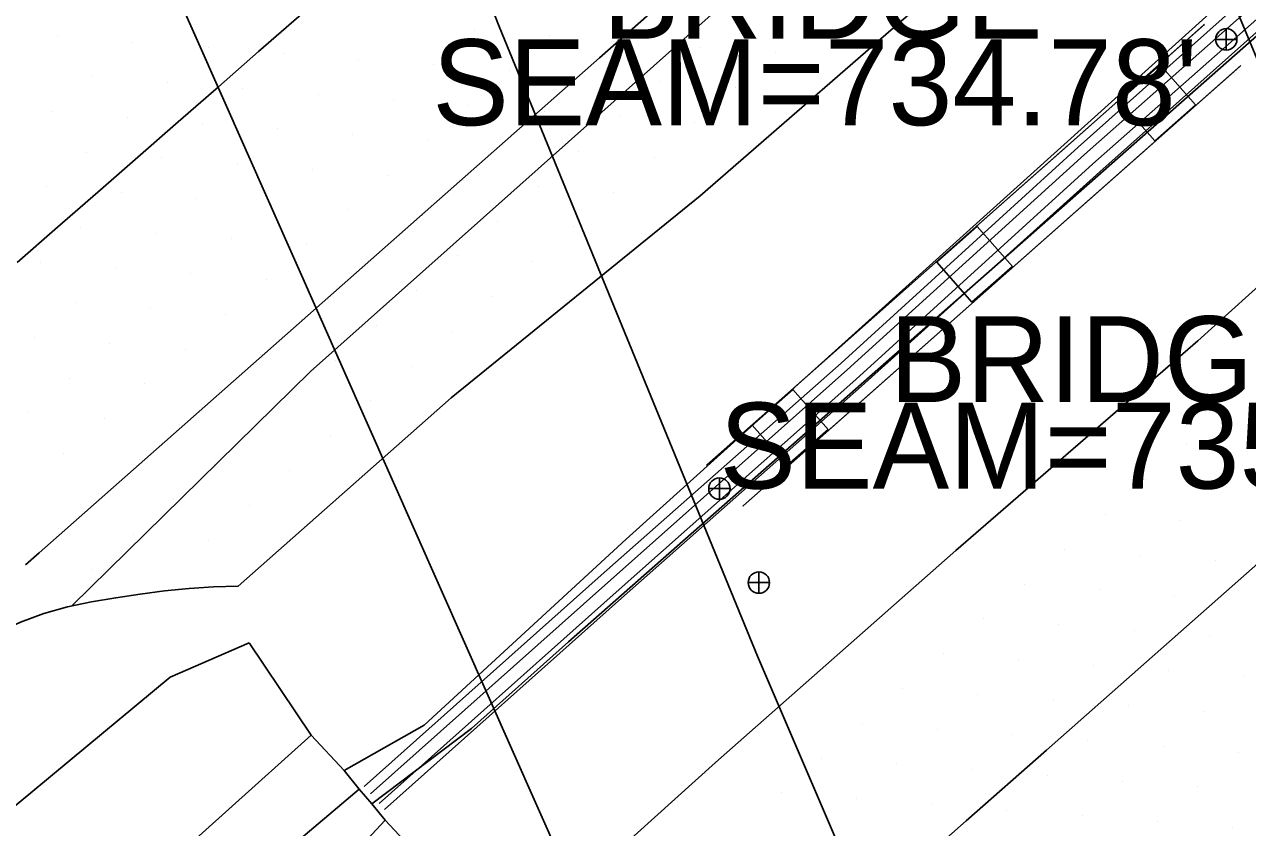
# Model space of a CAD drawing. Extents: x 1548934 to 1561348, y 809680 to 824075.
# Drawn here: x 1551783.3 to 1551840.5, y 810705.8 to 810743.4 of the extents above; entities that cross this region are included whole.
import ezdxf

# ---------------------------------------------------------------- set-up
doc = ezdxf.new("R2010")
doc.units = 0
for name, color, linetype in [('Default', 7, 'Continuous'), ('E_NCDOT_Vertical_Profile_Ground_Line', 7, 'Continuous'), ('Exist DTM Scan Elevation Point', 7, 'Continuous'), ('Exist Other Culture Area Outline', 7, 'Continuous'), ('Exist Structure Major Bridge Seam Top Elevation', 7, 'Continuous'), ('Exist Structure Major Deck Tunnel Box Culvert', 7, 'Continuous'), ('P_RDY_Terminator_Cell', 7, 'Continuous'), ('Pattern_8', 7, 'Continuous'), ('PH Exist DTM Breakline', 7, 'Continuous')]:
    doc.layers.add(name, color=color, linetype=linetype)

# ---------------------------------------------------------------- blocks, each defined once
blk = doc.blocks.new('SurveyPointCell')
at = {"layer": 'Default'}
for p, q in [((-0.5, 0), (0.5, 0)), ((0, -0.5), (0, 0.5))]:
    blk.add_line(p, q, dxfattribs=at)
blk.add_circle((0, 0), 0.5, dxfattribs=at)

msp = doc.modelspace()

# ---------------------------------------------------------------- linework, layer by layer
at = {"layer": 'E_NCDOT_Vertical_Profile_Ground_Line'}
for points in [[(1551730.822, 810673.853), (1551753.618, 810693.379), (1551776.873, 810712.355), (1551777.906, 810712.877), (1551778.938, 810713.401), (1551779.968, 810713.927), (1551780.996, 810714.457), (1551782.03, 810714.977), (1551783.082, 810715.455), (1551784.165, 810715.86), (1551785.276, 810716.172), (1551786.405, 810716.412), (1551787.541, 810716.606), (1551788.679, 810716.776), (1551789.821, 810716.924), (1551790.968, 810717.039), (1551792.121, 810717.111), (1551793.277, 810717.148), (1551803.243, 810725.955), (1551814.903, 810735.412), (1551826.218, 810745.259), (1551837.521, 810755.119), (1551848.5, 810765.046)], [(1551808.004, 810702.031), (1551815.623, 810708.894), (1551826.873, 810718.815), (1551838.214, 810728.632), (1551849.35, 810738.682)]]:
    msp.add_lwpolyline(points, dxfattribs=at)
at = {"layer": 'Exist DTM Scan Elevation Point'}
for p, q in [((1551804.334, 810743.172), (1551804.334, 810743.172)), ((1551784.81, 810742.88), (1551784.81, 810742.88)), ((1551788.335, 810742.612), (1551788.335, 810742.612)), ((1551807.86, 810742.905), (1551807.86, 810742.905)), ((1551811.387, 810742.639), (1551811.387, 810742.639)), ((1551791.86, 810742.345), (1551791.86, 810742.345)), ((1551795.386, 810742.077), (1551795.386, 810742.077)), ((1551814.914, 810742.373), (1551814.914, 810742.373)), ((1551818.442, 810742.107), (1551818.442, 810742.107)), ((1551798.912, 810741.81), (1551798.912, 810741.81)), ((1551802.438, 810741.543), (1551802.438, 810741.543)), ((1551805.964, 810741.276), (1551805.964, 810741.276)), ((1551786.439, 810740.983), (1551786.439, 810740.983)), ((1551789.964, 810740.716), (1551789.964, 810740.716)), ((1551809.49, 810741.01), (1551809.49, 810741.01)), ((1551813.018, 810740.744), (1551813.018, 810740.744)), ((1551793.49, 810740.449), (1551793.49, 810740.449)), ((1551797.015, 810740.181), (1551797.015, 810740.181)), ((1551816.545, 810740.479), (1551816.545, 810740.479)), ((1551800.541, 810739.914), (1551800.541, 810739.914)), ((1551804.067, 810739.647), (1551804.067, 810739.647)), ((1551784.542, 810739.354), (1551784.542, 810739.354)), ((1551788.068, 810739.087), (1551788.068, 810739.087)), ((1551807.594, 810739.381), (1551807.594, 810739.381)), ((1551811.121, 810739.115), (1551811.121, 810739.115)), ((1551791.593, 810738.82), (1551791.593, 810738.82)), ((1551795.119, 810738.553), (1551795.119, 810738.553)), ((1551814.649, 810738.85), (1551814.649, 810738.85)), ((1551798.645, 810738.286), (1551798.645, 810738.286)), ((1551802.171, 810738.019), (1551802.171, 810738.019)), ((1551786.171, 810737.458), (1551786.171, 810737.458)), ((1551805.698, 810737.752), (1551805.698, 810737.752)), ((1551809.225, 810737.486), (1551809.225, 810737.486)), ((1551789.697, 810737.191), (1551789.697, 810737.191)), ((1551793.223, 810736.924), (1551793.223, 810736.924)), ((1551812.753, 810737.221), (1551812.753, 810737.221)), ((1551796.749, 810736.657), (1551796.749, 810736.657)), ((1551800.275, 810736.39), (1551800.275, 810736.39)), ((1551803.801, 810736.123), (1551803.801, 810736.123)), ((1551784.275, 810735.829), (1551784.275, 810735.829)), ((1551787.8, 810735.562), (1551787.8, 810735.562)), ((1551807.328, 810735.857), (1551807.328, 810735.857)), ((1551810.855, 810735.591), (1551810.855, 810735.591)), ((1551791.326, 810735.295), (1551791.326, 810735.295)), ((1551794.852, 810735.028), (1551794.852, 810735.028)), ((1551798.378, 810734.761), (1551798.378, 810734.761)), ((1551801.905, 810734.494), (1551801.905, 810734.494)), ((1551785.904, 810733.933), (1551785.904, 810733.933)), ((1551805.432, 810734.228), (1551805.432, 810734.228)), ((1551808.959, 810733.963), (1551808.959, 810733.963)), ((1551789.43, 810733.666), (1551789.43, 810733.666)), ((1551792.956, 810733.399), (1551792.956, 810733.399)), ((1551796.482, 810733.132), (1551796.482, 810733.132)), ((1551800.008, 810732.865), (1551800.008, 810732.865)), ((1551784.008, 810732.304), (1551784.008, 810732.304)), ((1551803.536, 810732.6), (1551803.536, 810732.6)), ((1551807.063, 810732.333), (1551807.063, 810732.333)), ((1551787.534, 810732.037), (1551787.534, 810732.037)), ((1551791.06, 810731.77), (1551791.06, 810731.77)), ((1551794.585, 810731.503), (1551794.585, 810731.503)), ((1551798.112, 810731.236), (1551798.112, 810731.236)), ((1551801.639, 810730.97), (1551801.639, 810730.97)), ((1551785.637, 810730.408), (1551785.637, 810730.408)), ((1551805.168, 810730.706), (1551805.168, 810730.706)), ((1551789.163, 810730.141), (1551789.163, 810730.141)), ((1551792.689, 810729.874), (1551792.689, 810729.874)), ((1551796.215, 810729.607), (1551796.215, 810729.607)), ((1551799.743, 810729.341), (1551799.743, 810729.341)), ((1551783.741, 810728.779), (1551783.741, 810728.779)), ((1551803.27, 810729.076), (1551803.27, 810729.076)), ((1551839.82, 810728.913), (1551839.82, 810728.913)), ((1551787.267, 810728.512), (1551787.267, 810728.512)), ((1551790.793, 810728.245), (1551790.793, 810728.245)), ((1551794.319, 810727.979), (1551794.319, 810727.979)), ((1551797.846, 810727.712), (1551797.846, 810727.712)), ((1551801.374, 810727.447), (1551801.374, 810727.447)), ((1551785.37, 810726.883), (1551785.37, 810726.883)), ((1551788.896, 810726.616), (1551788.896, 810726.616)), ((1551792.423, 810726.35), (1551792.423, 810726.35)), ((1551795.95, 810726.084), (1551795.95, 810726.084)), ((1551799.477, 810725.817), (1551799.477, 810725.817)), ((1551783.474, 810725.254), (1551783.474, 810725.254)), ((1551839.551, 810725.386), (1551839.551, 810725.386)), ((1551787, 810724.987), (1551787, 810724.987)), ((1551790.527, 810724.721), (1551790.527, 810724.721)), ((1551794.054, 810724.455), (1551794.054, 810724.455)), ((1551797.582, 810724.189), (1551797.582, 810724.189)), ((1551837.655, 810723.757), (1551837.655, 810723.757)), ((1551785.103, 810723.358), (1551785.103, 810723.358)), ((1551788.63, 810723.092), (1551788.63, 810723.092)), ((1551792.158, 810722.826), (1551792.158, 810722.826)), ((1551795.685, 810722.56), (1551795.685, 810722.56)), ((1551835.759, 810722.128), (1551835.759, 810722.128)), ((1551839.282, 810721.859), (1551839.282, 810721.859)), ((1551786.734, 810721.463), (1551786.734, 810721.463)), ((1551790.261, 810721.197), (1551790.261, 810721.197)), ((1551793.789, 810720.931), (1551793.789, 810720.931)), ((1551833.862, 810720.499), (1551833.862, 810720.499)), ((1551837.386, 810720.23), (1551837.386, 810720.23)), ((1551784.837, 810719.834), (1551784.837, 810719.834)), ((1551788.364, 810719.568), (1551788.364, 810719.568)), ((1551791.892, 810719.302), (1551791.892, 810719.302)), ((1551831.966, 810718.87), (1551831.966, 810718.87)), ((1551835.49, 810718.601), (1551835.49, 810718.601)), ((1551786.468, 810717.939), (1551786.468, 810717.939)), ((1551839.013, 810718.332), (1551839.013, 810718.332)), ((1551830.07, 810717.241), (1551830.07, 810717.241)), ((1551833.593, 810716.973), (1551833.593, 810716.973)), ((1551837.117, 810716.704), (1551837.117, 810716.704)), ((1551828.173, 810715.613), (1551828.173, 810715.613)), ((1551831.697, 810715.344), (1551831.697, 810715.344)), ((1551835.221, 810715.075), (1551835.221, 810715.075)), ((1551838.745, 810714.806), (1551838.745, 810714.806)), ((1551826.277, 810713.984), (1551826.277, 810713.984)), ((1551829.801, 810713.715), (1551829.801, 810713.715)), ((1551833.324, 810713.446), (1551833.324, 810713.446)), ((1551836.848, 810713.177), (1551836.848, 810713.177)), ((1551840.373, 810712.909), (1551840.373, 810712.909)), ((1551824.381, 810712.355), (1551824.381, 810712.355)), ((1551827.904, 810712.086), (1551827.904, 810712.086)), ((1551831.428, 810711.817), (1551831.428, 810711.817)), ((1551834.952, 810711.548), (1551834.952, 810711.548)), ((1551838.477, 810711.28), (1551838.477, 810711.28)), ((1551822.484, 810710.726), (1551822.484, 810710.726)), ((1551826.008, 810710.457), (1551826.008, 810710.457)), ((1551829.532, 810710.188), (1551829.532, 810710.188)), ((1551833.056, 810709.919), (1551833.056, 810709.919)), ((1551836.58, 810709.651), (1551836.58, 810709.651)), ((1551840.105, 810709.383), (1551840.105, 810709.383)), ((1551820.588, 810709.097), (1551820.588, 810709.097)), ((1551824.112, 810708.828), (1551824.112, 810708.828)), ((1551827.635, 810708.559), (1551827.635, 810708.559)), ((1551831.159, 810708.29), (1551831.159, 810708.29)), ((1551818.691, 810707.468), (1551818.691, 810707.468)), ((1551834.684, 810708.022), (1551834.684, 810708.022)), ((1551838.208, 810707.754), (1551838.208, 810707.754)), ((1551822.215, 810707.199), (1551822.215, 810707.199)), ((1551825.739, 810706.93), (1551825.739, 810706.93)), ((1551829.263, 810706.661), (1551829.263, 810706.661)), ((1551832.787, 810706.393), (1551832.787, 810706.393)), ((1551836.312, 810706.125), (1551836.312, 810706.125)), ((1551839.837, 810705.857), (1551839.837, 810705.857))]:
    msp.add_line(p, q, dxfattribs=at)
at = {"layer": 'Exist Other Culture Area Outline'}
msp.add_lwpolyline([(1551793.783, 810714.49), (1551796.686, 810710.178), (1551798.234, 810708.524), (1551798.935, 810707.649), (1551799.527, 810706.96), (1551800.147, 810706.191), (1551801.479, 810704.775), (1551803.631, 810702.658), (1551805.5, 810701.282)], dxfattribs=at)
at = {"layer": 'Exist Structure Major Deck Tunnel Box Culvert'}
for points in [[(1551890.16, 810628.772), (1551869.489, 810674.52), (1551854.065, 810710.393), (1551839.842, 810744.541), (1551817.227, 810801.667), (1551801.118, 810844.761), (1551789.242, 810877.577)], [(1551763.353, 810854.68), (1551776.069, 810819.842), (1551783.152, 810800.687), (1551795.344, 810769.157), (1551805.495, 810743.337), (1551817.592, 810713.867), (1551830.145, 810684.596), (1551846.388, 810647.478), (1551862.114, 810612.886), (1551864.95, 810606.898)]]:
    msp.add_lwpolyline(points, dxfattribs=at)
for points in [[(1551838.515, 810743.432), (1551815.213, 810722.818), (1551815.213, 810722.818), (1551818.269, 810725.521), (1551818.269, 810725.521), (1551825.095, 810731.56), (1551825.095, 810731.56), (1551831.838, 810737.525), (1551831.838, 810737.525), (1551838.475, 810743.396)], [(1551840.22, 810741.511), (1551816.917, 810720.898), (1551816.917, 810720.898), (1551819.973, 810723.601), (1551819.973, 810723.601), (1551826.8, 810729.64), (1551826.8, 810729.64), (1551833.543, 810735.604), (1551833.543, 810735.604), (1551840.179, 810741.475)], [(1551838.094, 810739.67), (1551836.193, 810737.992), (1551834.543, 810739.861), (1551836.444, 810741.539)], [(1551829.529, 810732.115), (1551827.629, 810730.438), (1551825.979, 810732.307), (1551827.88, 810733.984)], [(1551820.895, 810724.485), (1551818.995, 810722.807), (1551817.345, 810724.676), (1551819.246, 810726.354)]]:
    msp.add_lwpolyline(points, close=True, dxfattribs=at)
at = {"layer": 'P_RDY_Terminator_Cell'}
for points in [[(1551854.512, 810780.962), (1551852.912, 810779.601), (1551849.914, 810776.954), (1551846.916, 810774.306), (1551840.17, 810768.349), (1551836.422, 810765.04), (1551832.674, 810761.73), (1551828.926, 810758.421), (1551825.178, 810755.111), (1551821.431, 810751.802), (1551817.683, 810748.492), (1551813.935, 810745.183), (1551810.187, 810741.873), (1551806.439, 810738.564), (1551802.692, 810735.254), (1551795.196, 810728.635), (1551791.448, 810725.326), (1551787.7, 810722.017), (1551783.953, 810718.707), (1551783.318, 810718.146)], [(1551820.539, 810765.242), (1551818.66, 810763.594), (1551816.78, 810761.945), (1551814.901, 810760.297), (1551813.021, 810758.648), (1551811.142, 810757), (1551809.262, 810755.352), (1551807.382, 810753.703), (1551805.503, 810752.055), (1551803.623, 810750.406), (1551801.744, 810748.758), (1551799.864, 810747.11), (1551797.985, 810745.461), (1551796.105, 810743.813), (1551794.226, 810742.164), (1551792.346, 810740.516), (1551790.463, 810738.872), (1551788.578, 810737.229), (1551786.694, 810735.586), (1551784.81, 810733.943), (1551782.925, 810732.3)], [(1551854.975, 810757.675), (1551843.796, 810747.674), (1551832.599, 810737.693), (1551821.511, 810727.588), (1551810.27, 810717.657), (1551799.168, 810707.769)], [(1551855.42, 810757.218), (1551844.155, 810747.31), (1551832.897, 810737.352), (1551821.785, 810727.271), (1551810.575, 810717.321), (1551799.474, 810707.426)], [(1551855.807, 810756.759), (1551844.541, 810746.851), (1551833.297, 810736.905), (1551822.186, 810726.825), (1551810.973, 810716.872), (1551799.873, 810706.978)], [(1551856.295, 810756.179), (1551844.812, 810746.522), (1551833.621, 810736.534), (1551822.461, 810726.511), (1551811.222, 810716.578), (1551800.129, 810706.691)], [(1551878.836, 810751.55), (1551876.115, 810749.151), (1551868.615, 810742.538), (1551864.865, 810739.231), (1551861.115, 810735.924), (1551857.365, 810732.617), (1551853.615, 810729.31), (1551849.865, 810726.003), (1551842.365, 810719.389), (1551838.615, 810716.082), (1551834.865, 810712.775), (1551831.115, 810709.468), (1551827.366, 810706.161), (1551823.616, 810702.854), (1551816.116, 810696.24), (1551812.366, 810692.933), (1551810.993, 810691.723)]]:
    msp.add_lwpolyline(points, dxfattribs=at)
at = {"layer": 'Pattern_8'}
msp.add_lwpolyline([(1551772.004, 810786.253), (1551837.927, 810637.788)], dxfattribs=at)
at = {"layer": 'PH Exist DTM Breakline'}
for points in [[(1551852.685, 810774.381), (1551844.675, 810768.929), (1551838.155, 810764.144), (1551796.663, 810727.191), (1551785.488, 810716.232)], [(1551854.933, 810757.899), (1551846.117, 810750.504), (1551840.309, 810745.37), (1551811.437, 810719.348), (1551801.976, 810710.638), (1551798.234, 810708.524)], [(1551799.527, 810706.96), (1551804.203, 810710.476), (1551808.738, 810714.535), (1551845.4, 810746.826), (1551853.036, 810753.543), (1551856.858, 810755.793)], [(1551793.783, 810714.49), (1551790.093, 810712.889), (1551775.841, 810701.081), (1551762.352, 810689.261), (1551753.824, 810678.927), (1551743.814, 810667.969), (1551739.115, 810653.932)], [(1551800.147, 810706.191), (1551795.43, 810701.1), (1551783.981, 810690.196), (1551775.177, 810682.226), (1551767.107, 810676.979), (1551757.362, 810669.525), (1551753.75, 810666.911), (1551751.818, 810666.221), (1551749.688, 810666.882), (1551749.215, 810667.944), (1551766.557, 810684.359), (1551776.213, 810693.39), (1551788.982, 810703.249), (1551796.686, 810710.178)], [(1551798.935, 810707.649), (1551785.169, 810695.999), (1551771.63, 810684.496), (1551762.849, 810677.327), (1551754.772, 810670.33), (1551749.688, 810666.882)]]:
    msp.add_lwpolyline(points, dxfattribs=at)

# ---------------------------------------------------------------- block references
at = {"layer": 'Default'}
for p in [(1551839.539, 810742.74), (1551815.805, 810721.712), (1551817.652, 810717.311)]:
    msp.add_blockref('SurveyPointCell', p, dxfattribs=at)

# ---------------------------------------------------------------- texts
at = {"layer": 'Exist Structure Major Bridge Seam Top Elevation'}
for s, p in [('BRIDGE', (1551810.331, 810742.767)), ("SEAM=734.78'", (1551802.36, 810738.72)), ('BRIDGE', (1551823.778, 810725.76)), ("SEAM=735.90'", (1551815.807, 810721.713))]:
    msp.add_text(s, height=4.02, dxfattribs=at).set_placement(p)

doc.saveas('drawing.dxf')
